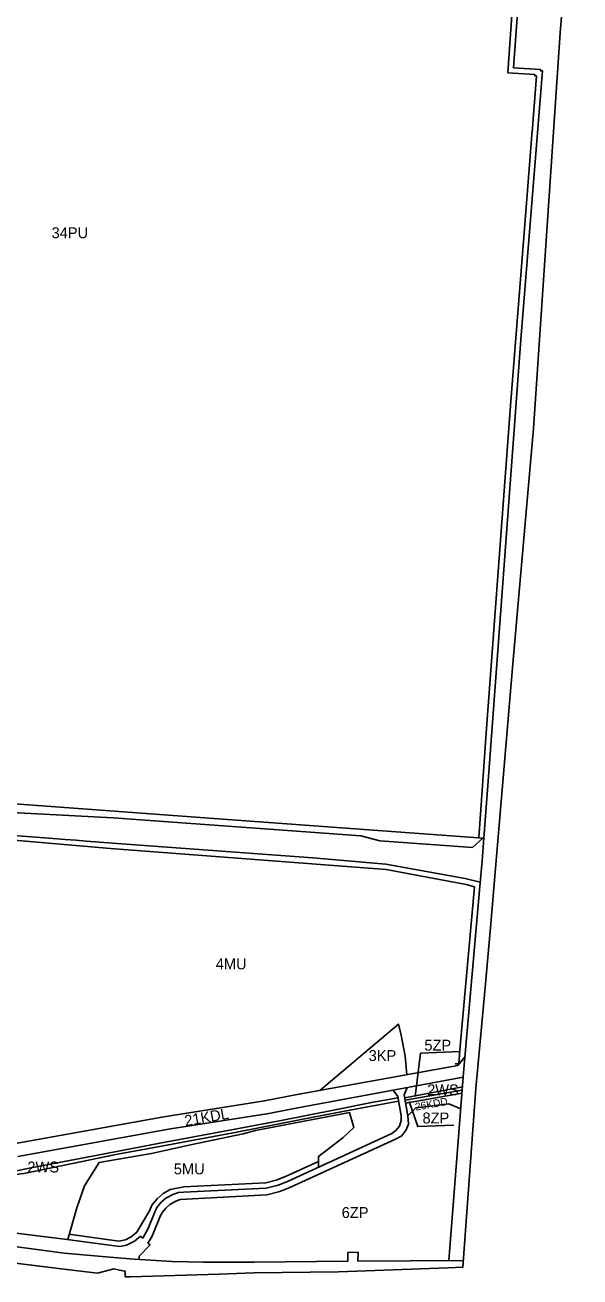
# Model space of a CAD drawing. Extents: x 7428203 to 7432868, y 5542672 to 5545406.
# Drawn here: x 7432333 to 7432841, y 5542811 to 5543958 of the extents above; entities that cross this region are included whole.
import ezdxf

# ---------------------------------------------------------------- set-up
doc = ezdxf.new("R2010")
doc.units = 0
for name, color, linetype in [('__LEGENDA_RAMKA_LOGO_PODZIAŁKA', 7, 'Continuous'), ('_GRANICA_MIASTA', 7, 'Continuous'), ('granicaBulwary', 7, 'Continuous'), ('MPZP_uchwalone_nieobowiazujace jeszcze_SZRAF', 7, 'Continuous')]:
    doc.layers.add(name, color=color, linetype=linetype)

msp = doc.modelspace()

# ---------------------------------------------------------------- linework, layer by layer
at = {"layer": '__LEGENDA_RAMKA_LOGO_PODZIAŁKA'}
msp.add_lwpolyline([(7432299.2, 5542826.7), (7432366.1, 5542818.4), (7432399.4, 5542814.2), (7432414.5, 5542818.4), (7432419.7, 5542817.2), (7432424.7, 5542816.2), (7432424.8, 5542810.9), (7432429.5, 5542811), (7432510.9, 5542813.5), (7432542.5, 5542814.5), (7432620.2, 5542815.7), (7432720.3, 5542819.2), (7432733.8, 5542819.8), (7432745.9, 5542983.6), (7432754.3, 5543076), (7432759.3, 5543131.1), (7432779.7, 5543372.7), (7432798.6, 5543588.3), (7432823.1, 5543950.8), (7432841.1, 5544172.5)], dxfattribs=at)
at = {"layer": '_GRANICA_MIASTA'}
for p, q in [((7432841.1, 5544172.5), (7432823.1, 5543950.8)), ((7432823.1, 5543950.8), (7432798.6, 5543588.3)), ((7432798.6, 5543588.3), (7432779.7, 5543372.7)), ((7432779.7, 5543372.7), (7432759.3, 5543131.1)), ((7432505.9, 5543230.9), (7432225, 5543251.4)), ((7432752.3, 5543212.9), (7432505.9, 5543230.9)), ((7432425.6, 5543207.4), (7432388.9, 5543210.1)), ((7432425.6, 5543207.4), (7432596.5, 5543194.9)), ((7432751.5, 5543192), (7432753.2, 5543212.9)), ((7432753.2, 5543212.9), (7432752.3, 5543212.9)), ((7432751.5, 5543192), (7432749.2, 5543165.2)), ((7432749.2, 5543165.2), (7432734.6, 5542997.9)), ((7432759.3, 5543131.1), (7432754.3, 5543076)), ((7432754.3, 5543076), (7432745.9, 5542983.6)), ((7432735.9, 5543012.8), (7432729.3, 5543004.6)), ((7432585.5, 5542978.6), (7432729.3, 5543004.6)), ((7432587.7, 5542966.8), (7432734.3, 5542993.9)), ((7432734.6, 5542997.9), (7432721.1, 5542826)), ((7432572.7, 5542976.1), (7432585.3, 5542978.6)), ((7432674.3, 5542976.1), (7432670.1, 5542982)), ((7432680.2, 5542977.8), (7432682.9, 5542984.4)), ((7432680.2, 5542977.8), (7432683.5, 5542958.6)), ((7432680.7, 5542975.1), (7432733.6, 5542985)), ((7432681.1, 5542972.8), (7432733.4, 5542982)), ((7432733.2, 5542979.4), (7432681.5, 5542970.2)), ((7432745.9, 5542983.6), (7432733.8, 5542819.8)), ((7432575, 5542964.4), (7432587.6, 5542966.8)), ((7432674.3, 5542976.1), (7432677.4, 5542958.5)), ((7432466.4, 5542946.5), (7432554.3, 5542960.2)), ((7432554.3, 5542960.2), (7432554.8, 5542960.3)), ((7432554.8, 5542960.3), (7432575, 5542964.4)), ((7432575, 5542964.4), (7432575, 5542964.4)), ((7432677.4, 5542958.5), (7432677.4, 5542954.2)), ((7432690.9, 5542965.8), (7432683.5, 5542958.6)), ((7432683.5, 5542958.6), (7432684, 5542950.7)), ((7432466.4, 5542946.5), (7432326.4, 5542921.2)), ((7432672.5, 5542945), (7432668.9, 5542942.3)), ((7432675.9, 5542949), (7432672.5, 5542945)), ((7432677.4, 5542954.2), (7432675.9, 5542949)), ((7432682, 5542945.6), (7432677.9, 5542940.1)), ((7432684, 5542950.7), (7432682, 5542945.6)), ((7432672.1, 5542937.2), (7432575.6, 5542892.8)), ((7432668.9, 5542942.3), (7432622.6, 5542921)), ((7432677.9, 5542940.1), (7432672.1, 5542937.2)), ((7432622.6, 5542921), (7432573.3, 5542898.3)), ((7432573.3, 5542898.3), (7432564.7, 5542895)), ((7432468.3, 5542886.5), (7432462.1, 5542883)), ((7432473.7, 5542888.2), (7432468.3, 5542886.5)), ((7432478.3, 5542888.5), (7432473.7, 5542888.2)), ((7432554.6, 5542886.2), (7432475.1, 5542881.7)), ((7432553.7, 5542892.2), (7432478.3, 5542888.5)), ((7432564.7, 5542895), (7432553.7, 5542892.2)), ((7432566.5, 5542889.3), (7432554.6, 5542886.2)), ((7432575.6, 5542892.8), (7432566.5, 5542889.3)), ((7432453.7, 5542874.5), (7432451.5, 5542869.5)), ((7432457.7, 5542879.3), (7432453.7, 5542874.5)), ((7432462.1, 5542883), (7432457.7, 5542879.3)), ((7432465.6, 5542877.2), (7432461.9, 5542873.8)), ((7432471.2, 5542880.3), (7432465.6, 5542877.2)), ((7432475.1, 5542881.7), (7432471.2, 5542880.3)), ((7432451.5, 5542869.5), (7432445.9, 5542855.3)), ((7432457, 5542867.2), (7432451.3, 5542852.7)), ((7432459.3, 5542870.5), (7432457, 5542867.2)), ((7432461.9, 5542873.8), (7432459.3, 5542870.5)), ((7432371.5, 5542845.2), (7432259.2, 5542859)), ((7432445.9, 5542855.3), (7432442.7, 5542849.8)), ((7432451.3, 5542852.7), (7432449.3, 5542847.5)), ((7432368.9, 5542832.7), (7432253, 5542848)), ((7432410.3, 5542840.1), (7432371.5, 5542845.2)), ((7432419.9, 5542838.9), (7432410.3, 5542840.1)), ((7432426, 5542840.1), (7432419.9, 5542838.9)), ((7432433.4, 5542843.7), (7432426, 5542840.1)), ((7432438.7, 5542848.2), (7432433.4, 5542843.7)), ((7432447.7, 5542840.3), (7432437.7, 5542829.9)), ((7432440.8, 5542846.4), (7432438.7, 5542848.2)), ((7432442.7, 5542849.8), (7432440.8, 5542846.4)), ((7432449.3, 5542847.5), (7432445.6, 5542841.8)), ((7432445.6, 5542841.8), (7432447.7, 5542840.3)), ((7432410.8, 5542829), (7432368.9, 5542832.7)), ((7432433, 5542827.3), (7432410.8, 5542829)), ((7432437.7, 5542829.9), (7432437.5, 5542827)), ((7432366.1, 5542818.4), (7432299.2, 5542826.7)), ((7432399.4, 5542814.2), (7432366.1, 5542818.4)), ((7432414.5, 5542818.4), (7432399.4, 5542814.2)), ((7432419.7, 5542817.2), (7432414.5, 5542818.4)), ((7432424.7, 5542816.2), (7432419.7, 5542817.2)), ((7432720.3, 5542819.2), (7432620.2, 5542815.7)), ((7432733.8, 5542819.8), (7432720.3, 5542819.2)), ((7432424.8, 5542810.9), (7432424.7, 5542816.2)), ((7432429.5, 5542811), (7432424.8, 5542810.9)), ((7432510.9, 5542813.5), (7432429.5, 5542811)), ((7432542.5, 5542814.5), (7432510.9, 5542813.5)), ((7432620.2, 5542815.7), (7432542.5, 5542814.5))]:
    msp.add_line(p, q, dxfattribs=at)
for points in [[(7432802.7, 5544225.3), (7432780.3, 5543918.7), (7432805.1, 5543917), (7432805.1, 5543916), (7432806.7, 5543915.9), (7432787.3, 5543673.7), (7432757.8, 5543273.2), (7432753.2, 5543212.9)], [(7432049.8, 5543256.2), (7432136.4, 5543244.6), (7432186, 5543244.4), (7432216.2, 5543242), (7432413.9, 5543231.5), (7432640.4, 5543214.9), (7432658, 5543210.5), (7432742.6, 5543204.3), (7432752.3, 5543212.9)], [(7432388.9, 5543210.1), (7432379.7, 5543211), (7432369.9, 5543211.7), (7432351.2, 5543213.1), (7432301.3, 5543216.8), (7432174.3, 5543226.5), (7432071.7, 5543238.2)], [(7432749.9, 5543172.5), (7432736.1, 5543175.9), (7432663.4, 5543189.2), (7432596.5, 5543194.9)], [(7432682.5, 5542996.1), (7432681.1, 5543013.1), (7432677.4, 5543032.4), (7432674.9, 5543042.6), (7432603.1, 5542981.8)], [(7432184.4, 5542881.8), (7432235.3, 5542891), (7432294.3, 5542901.7), (7432338.5, 5542910.7), (7432389.9, 5542920.7), (7432456.4, 5542933.5), (7432500.7, 5542941.8), (7432565.9, 5542954), (7432618.4, 5542964.4), (7432650.2, 5542970.6), (7432674.5, 5542974.9)], [(7432675, 5542972), (7432630.3, 5542963.8), (7432596.8, 5542957.2), (7432567.4, 5542951.4), (7432527, 5542943.4), (7432451.2, 5542929.6), (7432416.1, 5542923.1)], [(7432460.1, 5542957.7), (7432552.4, 5542972.1), (7432572.7, 5542976.1)], [(7432690.9, 5542965.8), (7432721.2, 5542969.5), (7432732, 5542964.8)], [(7432460.1, 5542957.7), (7432324.3, 5542933), (7432250.9, 5542920)], [(7432601.9, 5542911.5), (7432601.7, 5542921.3), (7432624.2, 5542938.7), (7432634, 5542947.9), (7432630.2, 5542961.5), (7432544, 5542945.2), (7432532.7, 5542942), (7432484.6, 5542932), (7432448.8, 5542924.1), (7432416.8, 5542918.6), (7432400.8, 5542915.7), (7432387.6, 5542894.5), (7432380.5, 5542874.3), (7432372.2, 5542845.1)], [(7432416.1, 5542923.1), (7432367.7, 5542913), (7432332.1, 5542905.7), (7432320.2, 5542904.1), (7432300.6, 5542900.2), (7432244.3, 5542890.1), (7432184.9, 5542878.8)], [(7432433, 5542827.3), (7432467.9, 5542825.1), (7432496.6, 5542824.4), (7432542.7, 5542824.5), (7432628.5, 5542825.2), (7432628.5, 5542833.2), (7432638, 5542833.5), (7432637.9, 5542825.2), (7432734.3, 5542826.1)]]:
    msp.add_lwpolyline(points, dxfattribs=at)
for centre, radius, start, end in [((7432585.8, 5542976.6), 2.07, 97.7776, 104.8422), ((7432572.7, 5542976.2), 0.112, 259.6952, 296.5651), ((7432587.6, 5542967), 0.231, 265.0303, 287.6501)]:
    msp.add_arc(centre, radius, start, end, dxfattribs=at)
at = {"layer": 'granicaBulwary'}
for points in [[(7432731.4, 5543017.3), (7432695.2, 5543015.8), (7432690.2, 5542976.2)], [(7432725.7, 5542949.9), (7432692.6, 5542948.6), (7432684.8, 5542971.5)]]:
    msp.add_lwpolyline(points, dxfattribs=at)
at = {"layer": 'MPZP_uchwalone_nieobowiazujace jeszcze_SZRAF'}
for points in [[(7432797.5, 5543859.7), (7432801.3, 5543911.2), (7432799.8, 5543911.4), (7432799.8, 5543912.4), (7432775, 5543914.1), (7432780.4, 5543989)], [(7432748.5, 5543213.2), (7432755.7, 5543313.3), (7432777.8, 5543613.2), (7432791.5, 5543786.8), (7432797.4, 5543861.1)], [(7432411.3, 5543203.5), (7432319.6, 5543211.2), (7432310.1, 5543203.3), (7432305.7, 5543061.8), (7432181.5, 5543067.1)], [(7432744.5, 5543168.4), (7432736.8, 5543170.5), (7432663.6, 5543184.1), (7432411.2, 5543203.5), (7432411.2, 5543203.5)], [(7432727, 5543006.2), (7432730.3, 5543006.1), (7432731.5, 5543022.4), (7432744.5, 5543168.4)], [(7432373.3, 5542850), (7432418.9, 5542843.8), (7432425, 5542845), (7432430.1, 5542847.5), (7432435.4, 5542852), (7432446.9, 5542871.6), (7432449.2, 5542876.5), (7432453.9, 5542882.5), (7432459.6, 5542887.4), (7432465.9, 5542890.9), (7432478.5, 5542893.5), (7432553.5, 5542897.2), (7432562.9, 5542899.7), (7432571.5, 5542903), (7432601.8, 5542916.5)]]:
    msp.add_lwpolyline(points, dxfattribs=at)

# ---------------------------------------------------------------- texts
at = {"layer": 'granicaBulwary'}
for s, p in [('34PU', (7432357.4, 5543762.5)), ('4MU', (7432507.7, 5543092.7)), ('5ZP', (7432698.7, 5543018.2)), ('3KP', (7432647.7, 5543008.7)), ('2WS', (7432701.2, 5542977.3)), ('8ZP', (7432697, 5542951.5)), ('2WS', (7432335.2, 5542906.6)), ('5MU', (7432469.3, 5542904.9)), ('6ZP', (7432623, 5542864.9))]:
    msp.add_text(s, height=10, dxfattribs=at).set_placement(p)
for s, height, rotation, p in [('26KDD', 7, 10.0718, (7432690.8, 5542963.2)), ('21KDL', 10, 9.876, (7432480, 5542948.9))]:
    msp.add_text(s, height=height, rotation=rotation, dxfattribs=at).set_placement(p)

doc.saveas('drawing.dxf')
